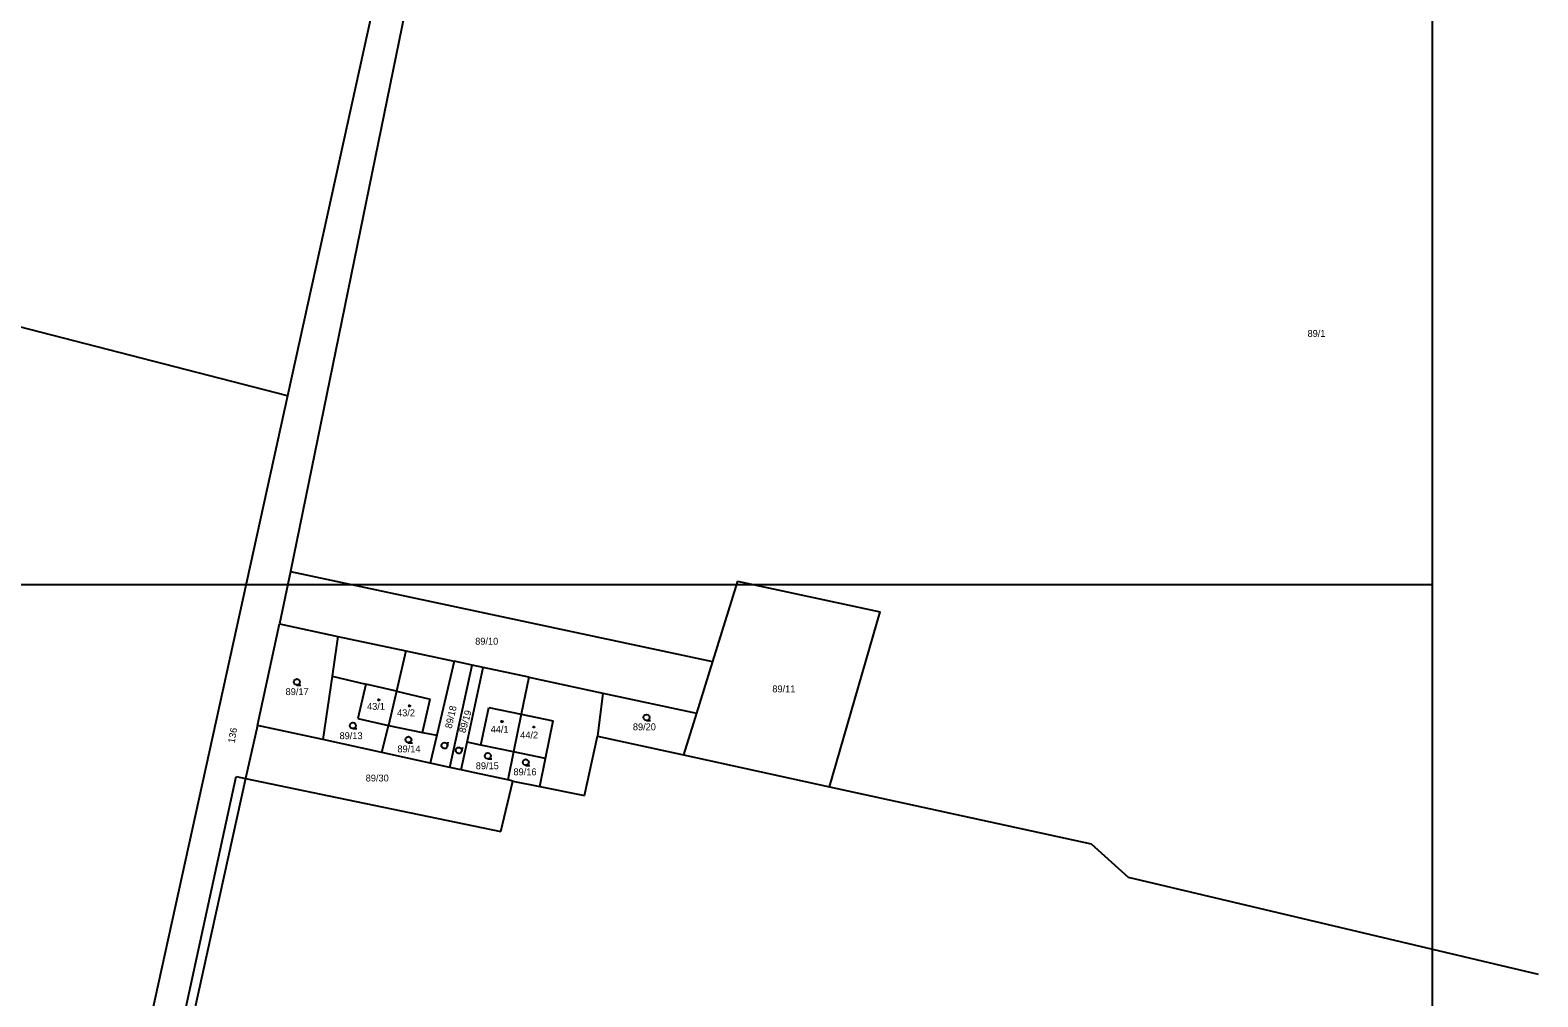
# Model space of a CAD drawing. Extents: x -752500 to -750336, y -1035826 to -1033500.
# Drawn here: x -751596.3 to -751224, y -1034101.8 to -1033863.2 of the extents above; entities that cross this region are included whole.
import ezdxf

# ---------------------------------------------------------------- set-up
doc = ezdxf.new("R2010")
doc.units = 0
for name, color, linetype in [('Default', 7, 'Continuous'), ('Hranice parcel', 7, 'Continuous'), ('ML1000', 7, 'Continuous'), ('Parcelní čísla', 7, 'Continuous'), ('Vnitřní kresba', 7, 'Continuous'), ('Značky budov', 7, 'Continuous'), ('Značky kultur', 7, 'Continuous')]:
    doc.layers.add(name, color=color, linetype=linetype)

# ---------------------------------------------------------------- blocks, each defined once
blk = doc.blocks.new('304')
at = {"layer": 'Default'}
blk.add_lwpolyline([(0, 0), (-0.38, 0.1), (-0.65, 0.37), (-0.75, 0.74), (-0.65, 1.11), (-0.38, 1.38), (-0.01, 1.48), (0.36, 1.38), (0.63, 1.11), (0.73, 0.73), (0.63, 0.35), (0.36, 0.08), (-0.02, -0.02), (0.98, -0.02)], dxfattribs=at)
blk = doc.blocks.new('402')
at = {"layer": 'Default'}
blk.add_lwpolyline([(0.09, 0.15), (0.18, 0), (0.09, -0.15), (-0.09, -0.15), (-0.18, 0), (-0.09, 0.15), (0.09, 0.15)], dxfattribs=at)

msp = doc.modelspace()

# ---------------------------------------------------------------- linework, layer by layer
at = {"layer": 'Hranice parcel'}
for p, q in [((-751500.87, -1033808.86), (-751532.72, -1033953.48)), ((-751496.99, -1033825.66), (-751532.03, -1033996.81)), ((-751532.72, -1033953.48), (-751709, -1033908.01)), ((-751532.72, -1033953.48), (-751573.48, -1034138.53)), ((-751532.03, -1033996.81), (-751534.68, -1034009.77)), ((-751532.03, -1033996.81), (-751427.81, -1034019.05)), ((-751421.64, -1033999.17), (-751427.81, -1034019.05)), ((-751421.64, -1033999.17), (-751386.37, -1034006.76)), ((-751398.92, -1034049.94), (-751386.37, -1034006.76)), ((-751540.15, -1034034.8), (-751534.68, -1034009.77)), ((-751534.68, -1034009.77), (-751520.29, -1034012.84)), ((-751520.29, -1034012.84), (-751521.72, -1034022.66)), ((-751520.29, -1034012.84), (-751503.52, -1034016.42)), ((-751503.52, -1034016.42), (-751505.82, -1034026.39)), ((-751503.52, -1034016.42), (-751491.6, -1034018.97)), ((-751491.6, -1034018.97), (-751495.9, -1034037.23)), ((-751492.67, -1034045.16), (-751487.17, -1034019.91)), ((-751487.17, -1034019.91), (-751491.6, -1034018.97)), ((-751488.41, -1034038.97), (-751484.46, -1034020.49)), ((-751484.46, -1034020.49), (-751487.17, -1034019.91)), ((-751473.11, -1034022.92), (-751484.46, -1034020.49)), ((-751427.81, -1034019.05), (-751431.75, -1034031.76)), ((-751521.72, -1034022.66), (-751524.02, -1034038.32)), ((-751521.72, -1034022.66), (-751513.43, -1034024.61)), ((-751513.43, -1034024.61), (-751515.39, -1034033.09)), ((-751473.11, -1034022.92), (-751475, -1034032.05)), ((-751473.11, -1034022.92), (-751454.86, -1034026.82)), ((-751505.82, -1034026.39), (-751507.78, -1034034.85)), ((-751454.86, -1034026.82), (-751456.18, -1034037.47)), ((-751454.86, -1034026.82), (-751431.75, -1034031.76)), ((-751515.39, -1034033.09), (-751507.78, -1034034.85)), ((-751475, -1034032.05), (-751476.93, -1034041.35)), ((-751431.75, -1034031.76), (-751434.95, -1034042.09)), ((-751540.15, -1034034.8), (-751543.07, -1034047.89)), ((-751524.02, -1034038.32), (-751540.15, -1034034.8)), ((-751509.48, -1034041.49), (-751507.78, -1034034.85)), ((-751507.78, -1034034.85), (-751499.43, -1034036.52)), ((-751499.43, -1034036.52), (-751495.9, -1034037.23)), ((-751509.48, -1034041.49), (-751524.02, -1034038.32)), ((-751495.9, -1034037.23), (-751497.52, -1034044.1)), ((-751489.87, -1034045.77), (-751488.41, -1034038.97)), ((-751485.02, -1034039.67), (-751488.41, -1034038.97)), ((-751476.93, -1034041.35), (-751485.02, -1034039.67)), ((-751459.38, -1034052.1), (-751456.18, -1034037.47)), ((-751456.18, -1034037.47), (-751434.95, -1034042.09)), ((-751497.52, -1034044.1), (-751509.48, -1034041.49)), ((-751492.67, -1034045.16), (-751497.52, -1034044.1)), ((-751476.93, -1034041.35), (-751478.37, -1034048.27)), ((-751469.04, -1034042.99), (-751476.93, -1034041.35)), ((-751470.47, -1034049.88), (-751469.04, -1034042.99)), ((-751434.95, -1034042.09), (-751398.92, -1034049.94)), ((-751562.48, -1034125.82), (-751545.42, -1034047.4)), ((-751543.07, -1034047.89), (-751560.38, -1034126.29)), ((-751545.42, -1034047.4), (-751543.07, -1034047.89)), ((-751543.07, -1034047.89), (-751522.56, -1034052.16)), ((-751489.87, -1034045.77), (-751492.67, -1034045.16)), ((-751486.48, -1034046.51), (-751489.87, -1034045.77)), ((-751478.37, -1034048.27), (-751486.48, -1034046.51)), ((-751480.05, -1034061.02), (-751477.1, -1034048.55)), ((-751477.1, -1034048.55), (-751478.37, -1034048.27)), ((-751477.1, -1034048.55), (-751470.47, -1034049.88)), ((-751470.47, -1034049.88), (-751459.38, -1034052.1)), ((-751398.92, -1034049.94), (-751334.29, -1034064.01)), ((-751522.56, -1034052.16), (-751480.05, -1034061.02)), ((-751334.29, -1034064.01), (-751325.16, -1034072.27)), ((-751325.16, -1034072.27), (-751223.97, -1034096.23))]:
    msp.add_line(p, q, dxfattribs=at)
at = {"layer": 'ML1000'}
for points in [[(-751250, -1035000), (-751250, -1034500), (-751250, -1034000), (-751250, -1033500)], [(-752500, -1034000), (-751875, -1034000), (-751250, -1034000)]]:
    msp.add_lwpolyline(points, dxfattribs=at)
at = {"layer": 'Vnitřní kresba'}
for p, q in [((-751505.82, -1034026.39), (-751513.43, -1034024.61)), ((-751505.82, -1034026.39), (-751497.51, -1034028.34)), ((-751499.43, -1034036.52), (-751497.51, -1034028.34)), ((-751485.02, -1034039.67), (-751483.03, -1034030.38)), ((-751483.03, -1034030.38), (-751475, -1034032.05)), ((-751475, -1034032.05), (-751467.11, -1034033.69)), ((-751469.04, -1034042.99), (-751467.11, -1034033.69))]:
    msp.add_line(p, q, dxfattribs=at)

# ---------------------------------------------------------------- block references
at = {"layer": 'Značky budov'}
for p in [(-751510.19, -1034028.51), (-751502.58, -1034029.98), (-751479.77, -1034033.85), (-751471.9, -1034035.19)]:
    msp.add_blockref('402', p, dxfattribs=at)
at = {"layer": 'Značky kultur'}
for p in [(-751530.4, -1034024.83), (-751444.07, -1034033.58), (-751516.58, -1034035.58), (-751502.88, -1034039.06), (-751483.28, -1034043.07), (-751473.9, -1034044.65)]:
    msp.add_blockref('304', p, dxfattribs=at)
for p, rotation in [((-751493.27, -1034039.9), 80.729753), ((-751489.72, -1034041.16), 77.005528)]:
    msp.add_blockref('304', p, dxfattribs=dict(at, rotation=rotation))

# ---------------------------------------------------------------- texts
at = {"layer": 'Parcelní čísla'}
for s, p in [('89/1', (-751280.88, -1033938.89)), ('89/10', (-751486.39, -1034014.88)), ('89/17', (-751533.2, -1034027.32)), ('89/11', (-751413.03, -1034026.65)), ('43/1', (-751513.09, -1034030.96)), ('43/2', (-751505.68, -1034032.55)), ('89/13', (-751519.88, -1034038.2)), ('44/1', (-751482.57, -1034036.62)), ('44/2', (-751475.28, -1034038.03)), ('89/20', (-751447.46, -1034036.01)), ('89/14', (-751505.59, -1034041.47)), ('89/15', (-751486.25, -1034045.63)), ('89/30', (-751513.43, -1034048.65)), ('89/16', (-751476.94, -1034047.12))]:
    msp.add_text(s, height=1.7, dxfattribs=at).set_placement(p)
for s, rotation, p in [('89/18', 77.464, (-751492.2, -1034035.71)), ('89/19', 73.797, (-751488.83, -1034036.81)), ('136', 80.157, (-751545.78, -1034039.28))]:
    msp.add_text(s, height=1.7, rotation=rotation, dxfattribs=at).set_placement(p)

doc.saveas('drawing.dxf')
